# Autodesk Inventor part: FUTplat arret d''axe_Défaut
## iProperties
Shininess: 64.0
Length Units: 11269
Angle Units: 11279
Time Units: 11290
Mass Units: 11283
Length Display Precision: 3
Angle Display Precision: 2
Compacted: True
Part Number: FUTplat arret d''axe_Défaut
Document SubType Name: Modeling
Created: 2006-11
Material: Par défaut
Designer: profs_sti
Density: 0.0
Volumn: 0.0
Area: 0.0
PropertySet Name: Model Information
Control State: 0
Master: False
Checked Out: False
Author: profs_sti
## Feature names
1. Base1
